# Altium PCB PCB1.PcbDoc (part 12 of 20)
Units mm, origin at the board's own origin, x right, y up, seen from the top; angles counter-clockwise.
Board outline 294.51 x 138.18 mm, 12 copper layers (Top Layer 1 _Signal, L2_GND, L3_Signals, L4_GND, L5_POWER, L6_Signals, L7_GND, L8_Signals, L9_GND, L10_POWER, L11_GND, Bottom Layer_Signals), stack 1.788 mm thick; 1254 components, 836 nets, 5699 pads, 2073 vias.
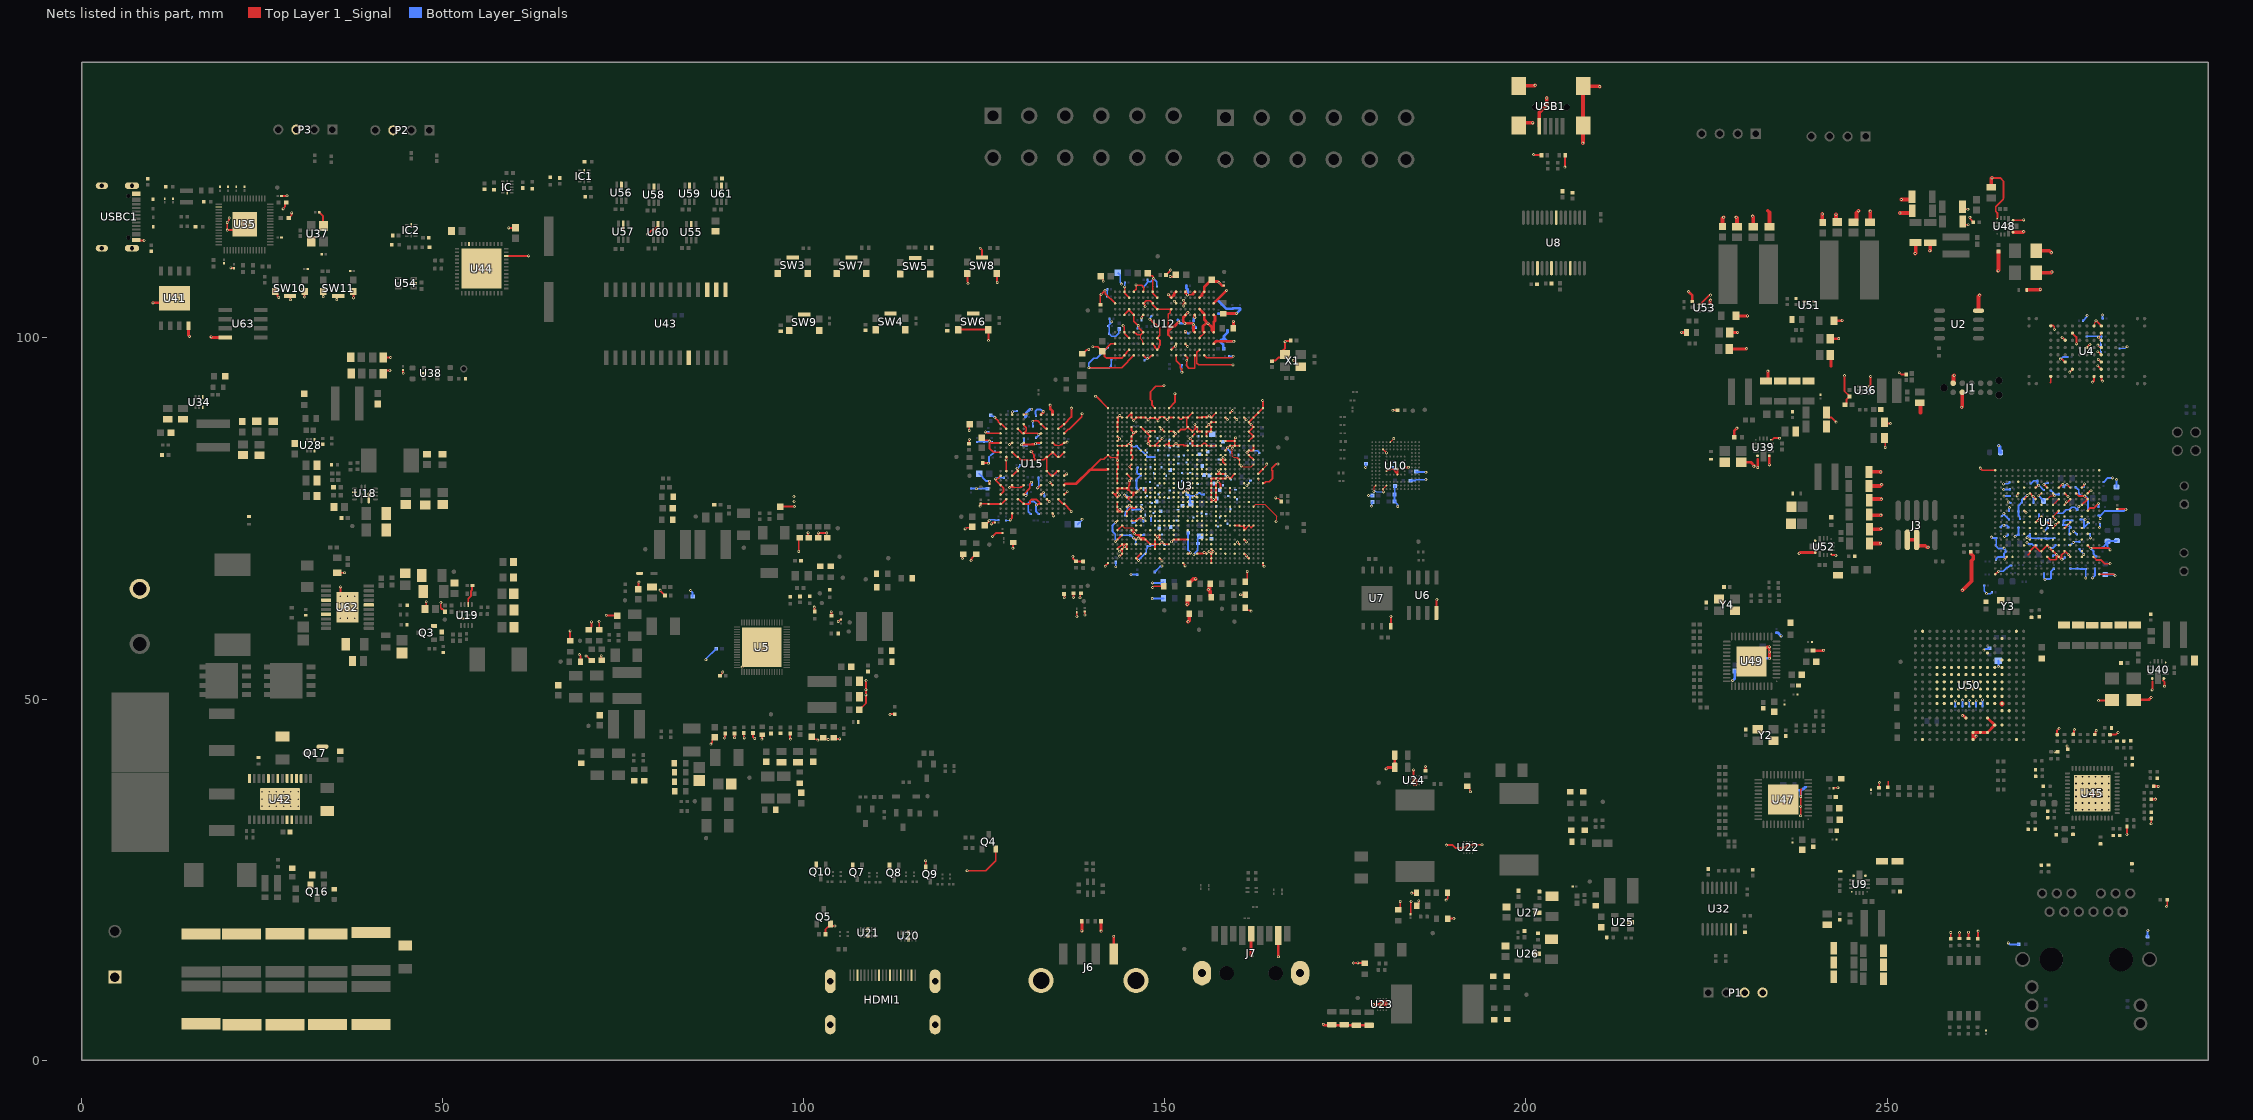
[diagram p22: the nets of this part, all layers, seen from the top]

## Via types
v1: diameter 0.4, hole 0.2, Top Layer 1 _Signal to Bottom Layer_Signals, 2009 vias
v2: diameter 0.508, hole 0.254, Top Layer 1 _Signal to Bottom Layer_Signals, 36 vias
v3: diameter 0.5, hole 0.2, Top Layer 1 _Signal to Bottom Layer_Signals, 12 vias
v4: diameter 1.27, hole 0.711, Top Layer 1 _Signal to Bottom Layer_Signals, 6 vias
v5: diameter 0.3, hole 0.2, Top Layer 1 _Signal to Bottom Layer_Signals, 5 vias
v6: diameter 0.254, hole 0.2, Top Layer 1 _Signal to Bottom Layer_Signals, 3 vias
v7: diameter 0.305, hole 0.2, Top Layer 1 _Signal to Bottom Layer_Signals, 1 vias
v8: diameter 0.254, hole 0.152, Top Layer 1 _Signal to Bottom Layer_Signals, 1 vias

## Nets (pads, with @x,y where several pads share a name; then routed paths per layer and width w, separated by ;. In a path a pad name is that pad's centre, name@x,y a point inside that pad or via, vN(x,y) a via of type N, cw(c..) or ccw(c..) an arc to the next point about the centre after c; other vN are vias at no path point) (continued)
GND: 1.1 2.1 3.1 4.1 5.1 6.1 C5.2 C6.1 C7.1 C8.1 C9.1 C10.1 C11.1 C12.1 C13.1 C14.1 C15.2 C16.1 C17.1 C18.2 C20.2 C21.2 C22.2 C23.2 C24.2 C25.2 C26.2 C27.1 C28.2 C29.2 C30.2 C31.1 C32.2 C33.2 C34.2 C35.2 C36.2 C37.2 C38.2 C39.2 C40.2 C41.2 C42.2 C43.1 C44.1 C46.2 C48.2 C49.2 C50.2 C52.2 C53.2 C54.2 C56.2 C57.2 C58.2 C59.2 C60.2 C61.2 C63.2 C64.2 C65.2 C66.2 C67.2 C68.2 C70.2 C71.2 C72.2 C73.2 C74.2 C75.2 C76.2 C77.2 C78.2 C79.2 C80.2 C81.2 C82.2 C83.2 C84.2 C85.2 C86.2 C87.2 C88.1 C89.2 C90.2 C91.2 C92.2 C93.2 C94.2 C95.2 C96.2 C97.1 C98.2 C99.2 C100.2 C101.2 C102.2 C103.2 C104.2 C105.2 C106.1 C107.2 C108.2 C111.2 C112.2 C113.2 C114.2 C115.2 C116.2 C117.2 C118.2 C119.2 C120.2 C121.1 C122.2 C123.2 C124.2 C125.2 C126.2 C127.2 C128.2 C129.2 C130.2 C131.2 C132.1 C133.1 C134.2 C135.2 C136.2 C137.2 C138.2 C139.2 C140.2 C141.2 C142.2 C143.2 C144.2 C145.2 C146.2 C147.2 C148.2 C149.2 C150.2 C151.2 C152.2 C153.2 C154.2 C155.2 C156.2 C158.2 C159.2 C160.2 C161.2 C162.2 C164.2 C165.2 C166.2 C167.2 C168.2 C169.2 C170.1 C171.2 C172.2 C173.2 C174.2 C175.2 C176.1 C177.1 C178.1 C180.2 C181.2 C182.2 C183.2 C184.1 C185.1 C187.2 C188.2 C189.2 C190.2 C191.2 C192.2 C194.1 C196.1 C197.1 C198.1 C199.1 C200.1 C201.1 C202.1 C203.2 C204.2 C205.1 C207.1 C208.1 C209.2 C210.1 C211.1 C212.2 C213.1 C214.1 C215.1 C216.1 C217.1 C220.1 C221.1 C222.2 C223.2 C224.2 C225.2 C226.2 C227.2 C228.2 C229.2 C230.1 C231.1 C232.1 C233.1 C234.2 C235.2 C236.1 C237.2 C238.2 C239.2 C240.2 C241.2 C242.2 C243.2 C244.2 C245.2 C246.2 C247.2 C248.2 C249.1 C250.2 C251.1 C252.1 C253.2 C254.2 C255.2 C256.1 C257.1 C258.2 C259.2 C260.1 C261.2 C262.1 C263.1 C264.2 C265.2 C266.2 C267.2 C268.2 C269.2 C270.2 C271.1 C272.1 C273.2 C274.2 C275.2 C276.2 C277.1 C278.1 C279.2 C280.2 C281.2 C282.1 C283.1 C284.1 C285.1 C286.2 C287.2 C288.2 C289.1 C290.1 C291.1 C292.2 C293.2 C294.2 C295.1 C296.1 C297.2 C298.1 C299.1 C300.1 C301.2 C302.1 C303.1 C304.1 C305.1 C306.2 C307.2 C308.1 C309.1 C310.1 C311.2 C312.2 C313.2 C314.1 C315.2 C316.2 C317.2 C318.2 C319.2 C320.2 C321.2 C322.2 C323.2 C324.2 C325.2 C326.2 C327.2 C328.2 C329.2 C330.2 C331.2 C332.2 C333.2 C334.2 C335.2 C336.2 C337.2 C338.2 C339.2 C340.2 C341.2 C342.2 C343.1 C344.2 C345.2 C346.2 C347.2 C348.2 C349.2 C350.2 C351.2 C352.1 C353.1 C354.2 C355.1 C356.2 C357.2 C358.2 C359.2 C360.2 C361.2 C362.2 C363.2 C364.2 C365.2 C366.2 C367.2 C368.2 C369.2 C370.2 C371.2 C372.2 C373.2 C374.2 C375.2 C376.2 C377.2 C378.2 C379.2 C380.2 C381.2 C382.2 C383.2 C384.2 C385.2 C386.2 C387.2 C388.2 C389.2 C390.2 C391.2 C392.2 C393.2 C394.2 C395.2 C396.2 C397.2 C398.2 C399.2 C400.2 C401.2 C402.2 C403.2 C404.2 C405.2 C406.2 C407.2 C408.2 C409.2 C410.2 C411.2 C412.2 C413.2 C414.2 C415.2 C416.2 C417.2 C418.2 C419.2 C420.2 C421.2 C422.2 C423.2 C424.2 C425.2 C426.2 C427.2 C428.2 C429.2 C430.2 C431.2 C432.2 C433.2 C434.2 C435.1 C437.1 C438.2 C439.2 C440.2 C441.2 C442.2 C443.2 C444.2 C446.2 C447.2 C448.2 C449.2 C450.2 C451.1 C452.2 C453.1 C454.2 C455.1 C456.2 C459.1 C460.2 C461.2 C462.1 C463.2 C464.2 C466.2 C467.2 C468.2 C470.2 C471.1 C472.1 C473.2 C483.2 C484.2 C485.1 C486.2 C487.1 C488.1 C489.2 C490.1 C491.1 C492.2 C493.1 C494.2 C495.2 C496.2 C497.2 C498.2 C500.1 C501.1 C502.2 C503.2 C504.2 C505.2 C506.2 C508.2 C509.1 C510.1 C511.2 C512.2 C513.2 C514.2 C515.2 C518.2 C519.2 C520.1 C521.1 C522.1 C523.1 C524.1 C525.1 C526.2 C528.2 C529.1 C530.1 C531.1 C532.1 C533.1 C534.1 C535.1 C536.1 C537.2 C538.1 C539.1 C540.1 C541.2 C542.2 C543.2 C544.1 C545.2 C547.2 C548.2 C550.2 C551.2 C552.2 C553.2 C554.2 C555.1 C556.1 C557.1 C558.1 C559.1 C560.2 C561.2 C562.1 C563.2 C564.1 C565.1 C566.1 C567.2 C568.1 C569.1 C570.1 C571.1 C572.1 C573.1 C574.1 C575.1 C576.1 C577.1 C578.1 C579.1 C580.1 C581.1 C582.1 C583.1 C584.1 C585.1 C586.2 C587.2 C588.1 C589.1 C590.1 C591.2 C592.1 C597.1 C598.2 C599.2 C600.1 C601.2 C603.2 C604.2 C605.2 C606.2 C611.1 C612.2 C613.1 C614.1 C615.2 C616.2 C617.2 C618.2 C619.1 C620.1 C621.1 C622.1 C623.1 C624.1 C625.1 C626.2 C627.1 C628.2 C629.2 C632.2 C635.1 C636.1 C637.2 C638.1 C639.1 C640.1 C641.2 C642.2 C643.2 C644.2 C645.2 C646.2 C647.2 C648.2 C649.1 C650.1 C651.2 C652.2 C653.1 C654.2 C655.2 C656.1 C657.2 C658.2 C659.2 C660.2 C661.1 C662.2 C663.1 C664.1 C665.2 C666.2 C667.2 C668.2 C669.2 C671.2 C672.2 C673.2 C674.2 C675.2 C676.2 C677.2 C679.2 C680.2 C681.2 C682.2 C683.2 C684.2 C685.2 C686.2 CN1.1 D1.2 D2.2 D5.1 D6.2 HDMI1.2 HDMI1.5 HDMI1.8 HDMI1.11 HDMI1.17 HDMI1.20 HDMI1.21 HDMI1.22 HDMI1.23 IC1.6 IC2.6 IC.6 J1.2 J1.10 J3.3 J3.5 J6.4 J6.Shell J7.4 J7.7 J7.Shell J8.1 P1.3 P1.4 P2.3 P3.3 Q3.2 Q4.2 Q5.2 Q7.2 Q8.2 Q9.2 Q10.2 Q16.2 Q17.2 R4.1 R6.1 R16.1 R17.1 R18.1 R19.1 R20.1 R33.1 R37.1 R40.2 R42.2 R52.1 R53.1 R69.1 R75.1 R76.2 R86.1 R88.1 R90.1 R91.1 R98.1 R99.1 R104.2 R105.1 R123.1 R126.2 R129.1 R131.1 R132.1 R134.2 R135.2 R137.1 R138.1 R142.1 R143.1 R144.2 R147.1 R157.1 R159.1 R162.1 R163.1 R176.2 R186.1 R190.2 R192.1 R210.1 R211.1 R212.2 R213.1 R215.2 R230.1 R233.1 R234.1 R235.2 R250.2 R256.1 R266.1 R267.1 R270.1 R271.1 R285.2 R297.1 R298.1 R302.1 R339.2 R375.1 R377.1 R382.1 R384.1 R386.1 R388.1 R390.1 R392.1 R394.1 R396.1 R397.1 R399.2 R402.1 SW3.3 SW3.4 SW3.5 SW4.3 SW4.4 SW4.5 SW5.3 SW5.4 SW5.5 SW6.3 SW6.4 SW6.5 SW7.3 SW7.4 SW7.5 SW8.3 SW8.4 SW8.5 SW9.3 SW9.4 SW9.5 SW10.1 SW10.2 SW10.5 SW11.1 SW11.2 SW11.5 U1.A1 U1.A19 U1.B16 U1.C5 U1.C6 U1.C8 U1.C10 U1.C12 U1.C14 U1.D4 U1.D7 U1.D9 U1.D11 U1.D13 U1.D15 U1.D16 U1.E5 U1.F4 U1.F6 U1.F8 U1.F10 U1.F12 U1.F14 U1.F16 U1.G5 U1.G7 U1.G9 U1.G11 U1.G13 U1.G15 U1.H4 U1.H6 U1.H8 U1.H10 U1.H12 U1.H14 U1.H16 U1.J5 U1.J7 U1.J9 U1.J11 U1.J13 U1.J15 U1.K4 U1.K6 U1.K8 U1.K10 U1.K12 U1.K14 U1.K16 U1.L5 U1.L7 U1.L9 U1.L11 U1.L13 U1.L15 U1.M4 U1.M6 U1.M8 U1.M10 U1.M12 U1.M14 U1.N5 U1.N7 U1.N9 U1.N11 U1.N13 U1.N15 U1.P4 U1.P6 U1.P8 U1.P10 U1.P12 U1.P14 U1.R3 U1.R5 U1.T16 U1.U16 U1.W1 U1.W19 U2.4 U3.A1 U3.A11 U3.A14 U3.A34 U3.AA3 U3.AA6 U3.AA8 U3.AA10 U3.AA11 U3.AA16 U3.AA17 U3.AA18 U3.AA19 U3.AA20 U3.AA21 U3.AA22 U3.AA23 U3.AA24 U3.AA31 U3.AB3 U3.AB5 U3.AB6 U3.AB7 U3.AB8 U3.AB10 U3.AB11 U3.AB16 U3.AB17 U3.AB18 U3.AB19 U3.AB20 U3.AB24 U3.AB27 U3.AB29 U3.AB32 U3.AC3 U3.AC4 U3.AC5 U3.AC8 U3.AC10 U3.AC11 U3.AC12 U3.AC16 U3.AC20 U3.AC21 U3.AC24 U3.AC27 U3.AD5 U3.AD8 U3.AD10 U3.AD11 U3.AD12 U3.AD16 U3.AD20 U3.AD21 U3.AD24 U3.AD25 U3.AD26 U3.AE3 U3.AE6 U3.AE7 U3.AE9 U3.AE11 U3.AE12 U3.AE13 U3.AE14 U3.AE15 U3.AE16 U3.AE18 U3.AE19 U3.AE20 U3.AE21 U3.AE24 U3.AE26 U3.AF4 U3.AF7 U3.AF8 U3.AF11 U3.AF12 U3.AF13 U3.AF14 U3.AF15 U3.AF16 U3.AF21 U3.AF22 U3.AF24 U3.AF25 U3.AF27 U3.AF28 U3.AF29 U3.AF30 U3.AF31 U3.AF32 U3.AG3 U3.AG6 U3.AG7 U3.AG10 U3.AG12 U3.AG15 U3.AG18 U3.AG21 U3.AG22 U3.AG30 U3.AH4 U3.AH8 U3.AH11 U3.AH12 U3.AH15 U3.AH21 U3.AH22 U3.AH23 U3.AJ3 U3.AJ7 U3.AJ8 U3.AJ9 U3.AJ11 U3.AJ12 U3.AJ15 U3.AJ16 U3.AJ18 U3.AJ21 U3.AJ22 U3.AJ23 U3.AJ30 U3.AK4 U3.AK5 U3.AK7 U3.AK10 U3.AK11 U3.AK12 U3.AK13 U3.AK14 U3.AK23 U3.AK28 U3.AK29 U3.AL3 U3.AL4 U3.AL5 U3.AL11 U3.AL13 U3.AL23 U3.AL25 U3.AM4 U3.AM8 U3.AM9 U3.AM18 U3.AM20 U3.AM22 U3.AM23 U3.AM24 U3.AM26 U3.AM28 U3.AM30 U3.AN7 U3.AN12 U3.AN23 U3.AN31 U3.AP1 U3.AP17 U3.AP23 U3.AP34 U3.B6 U3.B19 U3.B24 U3.B27 U3.B33 U3.C3 U3.C4 U3.C5 U3.C6 U3.C7 U3.C8 U3.C9 U3.C10 U3.C11 U3.C12 U3.C13 U3.C14 U3.C15 U3.C16 U3.C17 U3.C18 U3.C20 U3.C21 U3.C22 U3.C23 U3.C26 U3.C28 U3.C30 U3.C32 U3.D3 U3.D23 U3.D24 U3.D31 U3.E3 U3.E6 U3.E8 U3.E12 U3.E18 U3.E20 U3.E22 U3.E23 U3.E32 U3.F3 U3.F7 U3.F9 U3.F10 U3.F11 U3.F13 U3.F14 U3.F15 U3.F16 U3.F19 U3.F20 U3.F21 U3.F22 U3.F23 U3.F31 U3.G3 U3.G6 U3.G10 U3.G15 U3.G19 U3.G21 U3.G22 U3.G25 U3.G32 U3.H3 U3.H6 U3.H10 U3.H12 U3.H14 U3.H19 U3.H22 U3.H25 U3.H26 U3.H28 U3.H31 U3.J3 U3.J4 U3.J5 U3.J6 U3.J10 U3.J11 U3.J12 U3.J13 U3.J14 U3.J15 U3.J16 U3.J18 U3.J19 U3.J20 U3.J21 U3.J22 U3.J23 U3.J24 U3.J25 U3.J27 U3.J28 U3.J29 U3.J32 U3.K3 U3.K6 U3.K8 U3.K9 U3.K18 U3.K21 U3.K22 U3.K26 U3.K31 U3.K32 U3.L1 U3.L3 U3.L6 U3.L9 U3.L16 U3.L19 U3.L20 U3.L21 U3.L22 U3.L25 U3.L26 U3.L31 U3.M3 U3.M6 U3.M9 U3.M11 U3.M14 U3.M15 U3.M18 U3.M20 U3.M22 U3.M25 U3.M26 U3.M29 U3.M32 U3.N3 U3.N6 U3.N9 U3.N11 U3.N14 U3.N15 U3.N18 U3.N20 U3.N22 U3.N25 U3.N26 U3.N29 U3.N32 U3.P1 U3.P3 U3.P6 U3.P8 U3.P9 U3.P11 U3.P14 U3.P15 U3.P18 U3.P19 U3.P20 U3.P21 U3.P22 U3.P25 U3.P26 U3.P34 U3.R3 U3.R5 U3.R8 U3.R9 U3.R11 U3.R13 U3.R15 U3.R18 U3.R19 U3.R20 U3.R21 U3.R22 U3.R23 U3.R24 U3.R25 U3.R26 U3.R28 U3.R33 U3.T3 U3.T6 U3.T9 U3.T11 U3.T13 U3.T15 U3.T18 U3.T19 U3.T20 U3.T23 U3.T24 U3.T25 U3.T26 U3.T27 U3.T33 U3.U3 U3.U12 U3.U13 U3.U15 U3.U16 U3.U17 U3.U19 U3.U20 U3.U23 U3.U24 U3.U30 U3.U31 U3.U34 U3.V3 U3.V4 U3.V5 U3.V8 U3.V9 U3.V10 U3.V11 U3.V15 U3.V18 U3.V19 U3.V23 U3.V24 U3.V25 U3.V27 U3.V30 U3.W2 U3.W3 U3.W6 U3.W7 U3.W9 U3.W10 U3.W11 U3.W12 U3.W15 U3.W16 U3.W17 U3.W18 U3.W19 U3.W20 U3.W23 U3.W24 U3.W27 U3.Y3 U3.Y5 U3.Y6 U3.Y8 U3.Y9 U3.Y10 U3.Y11 U3.Y12 U3.Y13 U3.Y14 U3.Y15 U3.Y16 U3.Y17 U3.Y18 U3.Y19 U3.Y20 U3.Y23 U3.Y24 U3.Y28 U4.G2 U4.G3 U4.G4 U4.G5 U4.G6 U4.G7 U4.G8 U4.G9 U4.H2 U4.H9 U4.J5 U4.L3 U4.L8 U4.M4 U4.M7 U4.P2 U4.P9 U5.69 U6.4 U7.4 U8.7 U8.18 U8.21 U8.25 U9.1 U9.9 U9.11 U10.A6 U10.C4 U10.H10 U10.J5 U10.K8 U10.N2 U10.N5 U10.P4 U12.A3 U12.A10 U12.AB3 U12.AB5 U12.AB8 U12.AB10 U12.C1 U12.C5 U12.C8 U12.C12 U12.D2 U12.D4 U12.D9 U12.D11 U12.E1 U12.E5 U12.E8 U12.E12 U12.G1 U12.G3 U12.G5 U12.G8 U12.G10 U12.G12 U12.J1 U12.J3 U12.J10 U12.J12 U12.K2 U12.K4 U12.K9 U12.K11 U12.N2 U12.N4 U12.N9 U12.N11 U12.P1 U12.P3 U12.P10 U12.P12 U12.T1 U12.T3 U12.T5 U12.T8 U12.T10 U12.T12 U12.V1 U12.V5 U12.V8 U12.V12 U12.W2 U12.W4 U12.W9 U12.W11 U12.Y1 U12.Y5 U12.Y8 U12.Y12 U13.1 U14.1 U15.A3 U15.A10 U15.AB3 U15.AB5 U15.AB8 U15.AB10 U15.C1 U15.C5 U15.C8 U15.C12 U15.D2 U15.D4 U15.D9 U15.D11 U15.E1 U15.E5 U15.E8 U15.E12 U15.G1 U15.G3 U15.G5 U15.G8 U15.G10 U15.G12 U15.J1 U15.J3 U15.J10 U15.J12 U15.K2 U15.K4 U15.K9 U15.K11 U15.N2 U15.N4 U15.N9 U15.N11 U15.P1 U15.P3 U15.P10 U15.P12 U15.T1 U15.T3 U15.T5 U15.T8 U15.T10 U15.T12 U15.V1 U15.V5 U15.V8 U15.V12 U15.W2 U15.W4 U15.W9 U15.W11 U15.Y1 U15.Y5 U15.Y8 U15.Y12 U16.2 U17.2 U18.2 U18.10 U19.2 U19.10 U20.3 U20.8 U21.3 U21.8 U22.B2 U22.B3 U22.B4 U22.C1 U22.C2 U22.C3 U22.C4 U23.B2 U23.B3 U23.B4 U23.C1 U23.C2 U23.C3 U23.C4 U24.B2 U24.B3 U24.B4 U24.C1 U24.C2 U24.C3 U24.C4 U25.2 U26.2 U27.2 U28.3 U28.4 U29.2 U30.2 U31.2 U32.15 U33.2 U34.3 U34.4 U35.47 U35.61 U36.3 U37.2 U37.4 U38.2 U39.1 U39.9 U39.11 U40.1 U40.9 U40.11 U41.4 U41.9 U42.9 U42.10 U42.17 U42.18 U42.19 U42.20 U42.22 U42.24 U42.28 U42.29 U43.10 U43.15 U43.16 U43.17 U44.10 U44.46 U44.49 U45.49 U47.49 U48.1 U48.9 U48.11 U49.49 U50.B1 U50.B16 U50.C5 U50.C12 U50.D2 U50.D5 U50.D6 U50.D7 U50.D8 U50.D9 U50.D10 U50.D11 U50.D12 U50.D14 U50.E6 U50.E7 U50.E8 U50.E9 U50.E10 U50.E11 U50.E14 U50.F4 U50.F6 U50.F7 U50.F8 U50.F9 U50.F10 U50.F11 U50.F13 U50.F15 U50.G6 U50.G7 U50.G8 U50.G9 U50.G10 U50.G11 U50.G15 U50.H6 U50.H7 U50.H8 U50.H9 U50.H10 U50.H11 U50.H15 U50.H16 U50.J6 U50.J7 U50.J8 U50.J9 U50.J10 U50.J11 U50.J13 U50.K6 U50.K7 U50.K8 U50.K9 U50.K10 U50.K11 U50.L6 U50.L7 U50.L8 U50.L9 U50.L10 U50.L11 U50.M6 U50.M7 U50.M8 U50.M9 U50.M10 U50.M11 U50.N6 U50.N7 U50.N8 U50.N9 U50.N10 U50.N11 U50.R1 U50.R16 U51.3 U51.4 U52.1 U52.9 U52.11 U53.3 U53.4 U54.2 U55.2 U56.2 U57.2 U58.2 U59.2 U60.2 U61.2 U62.6 U62.14 U62.17 U62.21 U63.4 USB1.5 USB1.6 USB1.7 USB1.8 USB1.9 USBC1.A1_B12 USBC1.B1_A12 USBC1.S1 USBC1.S2 USBC1.S3 USBC1.S4 X1.2 X1.4 Y2.2 Y2.4 Y3.3 Y4.2 Y4.4 | length 1028.4
  Top Layer 1 _Signal w0.089: v1@178.963,78.776 178.963,79.406
  Top Layer 1 _Signal w0.132: 129.071,79.28 129.087,79.295 129.784,79.295 129.792,79.304 129.947,79.304 ; 135.029,85.146 135.511,85.146 135.548,85.183 ; 146.644,100.428 146.68,100.393 146.68,99.854 146.972,99.562 146.972,99.221 U12.G3@147.004,99.189 ; 178.963,79.406 179.007,79.406 179.172,79.57 U10.N2@179.204,79.57 ; v1(180.267,78.675) 180.226,78.716 180.226,79.047 U10.P4@180.204,79.07 U10.N5@180.704,79.57
  Top Layer 1 _Signal w0.152: 142.58,83.453 142.585,83.448 143.139,83.448 143.21,83.376 143.281,83.305 143.281,83.27 143.429,83.122 143.436,83.115 v1(143.436,83.048) ; U3.AF4@144.079,74.028 144.359,73.749 144.359,73.725 144.579,73.725 144.607,73.698 145.562,73.698 145.789,73.471 v1(145.789,72.899) ; v1(151.316,105.079) 151.316,105.053 151.554,104.815 U12.P10@151.554,104.789 ; v1(152.591,105.213) 152.641,105.163 152.641,105.055 152.854,104.842 U12.T10@152.854,104.789 152.755,104.888 152.629,104.888 152.539,104.799 152.539,104.491 v1(152.608,104.423) ; U3.W27@159.029,78.578 159.039,78.587 159.039,79.219 U3.V27@159.029,79.228 ; v1(159.372,84.748) 159.359,84.735 159.359,84.305 159.293,84.239 159.293,84.113 159.359,84.047 159.359,83.645 159.547,83.458 159.802,83.458 159.86,83.399 160.04,83.399 ; U3.M29@160.329,83.128 160.346,83.111 160.346,82.495 U3.N29@160.329,82.478 160.329,82.435 160.491,82.274 v1(160.585,82.274) 160.652,82.274 160.768,82.158 161.959,82.158 U3.N32@162.279,82.478 ; v1(161.372,84.113) 161.372,84.074 161.629,83.817 U3.L31@161.629,83.778 ; U3.AB32@162.279,76.628 162.599,76.948 163.815,76.948 165.483,75.28 165.483,74.67 v1(165.409,74.595) ; U3.T33@162.929,80.528 162.929,80.483 163.028,80.384 163.028,80.313 163.079,80.262 v6(163.079,80.235) ; U3.P34@163.579,81.828 164.06,82.308 164.06,82.473 v1(164.107,82.52) v1@164.107,82.5 ; v1(165.354,77.842) 165.402,77.794 165.693,77.794 166.121,77.365 R69.1@166.121,77.34 ; U10.A6@181.204,85.57 181.669,86.035 181.669,86.046 v1(181.692,86.07) ; v1(271.015,78.148) 271.032,78.148 271.364,78.48 U1.L5@271.381,78.48 ; U1.K6@272.181,77.68 272.678,78.177 v1(273.201,78.177) 273.201,78.218 272.981,78.438 U1.J5@272.981,78.48 ; U1.J7@272.981,76.88 273.017,76.88 273.429,77.292 273.429,77.328 U1.H6@273.781,77.68 ; U1.G7@274.581,76.88 274.868,77.167 274.868,77.293 v1(274.864,77.297) ; U4.H2@278.672,101.669 278.728,101.726 278.728,102.097 278.938,102.307 v1(278.938,102.374) ; v1(279.194,99) 279.468,98.726 279.615,98.726 U4.G5@279.672,98.669 ; U4.G4@279.672,99.669 279.308,100.033 v1(279.308,100.102) 279.615,100.409 279.615,100.612 U4.G3@279.672,100.669
  Top Layer 1 _Signal w0.178: v1(153.132,105.967) 153.809,105.967 153.892,106.051
  Top Layer 1 _Signal w0.2: U57.2@75.008,115.799 75.008,114.933 75.169,114.772 v1(75.169,114.718) ; v1(78.37,114.353) 78.995,114.978 79.286,114.978 79.823,115.516 U60.2@79.823,115.766 ; C16.1@137.804,62.001 137.808,61.997 137.808,61.447 v1(137.811,61.444) ; C430.2@138.566,97.817 138.641,97.817 139.195,98.371 139.418,98.371 v1(139.456,98.41) ; v1(139.47,95.877) 139.479,95.887 144.003,95.887 U12.E1@145.704,97.589 ; v1(140.019,98.78) 140.686,98.78 C340.2@141.306,98.16 141.656,98.51 141.924,98.51 142.047,98.633 142.047,98.709 142.527,99.189 U12.A3@143.104,99.189 ; C367.2@141.124,108.56 141.47,108.214 v1(141.47,107.842) ; v1(141.739,68.385) 141.739,68.437 U3.AP1@142.129,68.828 ; U3.AL3@143.429,70.778 U3.AK4@144.079,71.428 U3.AK4@144.095,71.428 ; v1(143.733,70.465) 144.047,70.778 U3.AL4@144.079,70.778 ; v1(143.743,69.792) U3.AM4@144.079,70.128 U3.AL4@144.079,70.778 ; v1(144.222,101.706) 144.222,101.652 144.404,101.47 U12.C5@144.404,100.789 144.433,100.76 144.433,100.61 U12.D4@145.054,99.989 ; v1(144.434,107.065) 144.419,107.05 144.419,106.404 U12.C12@144.404,106.389 144.433,106.36 144.433,106.21 U12.D11@145.054,105.589 ; v1(144.451,71.087) v1@144.436,71.087 ; U3.AL5@144.729,70.778 U3.AK5@144.729,71.428 U3.AK4@144.095,71.428 ; U12.E12@145.704,106.389 145.704,106.429 146.007,106.732 v1(146.007,107.345) 146.046,107.307 146.181,107.307 146.224,107.263 146.833,107.263 147.064,107.032 147.064,106.586 147.033,106.555 147.033,106.418 U12.G12@147.004,106.389 ; v1(146.743,102.786) 146.781,102.825 146.781,102.925 147.004,103.148 U12.G8@147.004,103.189 ; U12.G1@147.004,97.589 147.418,97.175 147.537,97.175 v1(147.576,97.137) 147.614,97.175 147.798,97.175 148.137,97.514 148.189,97.514 148.264,97.589 U12.J1@148.304,97.589 U12.J1@148.304,97.623 ; C316.2@147.62,108.922 147.919,108.622 148.244,108.622 148.415,108.452 148.415,108.25 v1(148.453,108.211) 148.453,108.157 148.304,108.008 U12.J12@148.304,106.389 148.333,106.36 148.333,106.21 U12.K11@148.954,105.589 ; v1(147.924,102.587) 147.957,102.587 148.548,101.995 148.7,101.995 149.313,101.381 149.313,100.348 U12.K4@148.954,99.989 ; U3.E12@149.279,87.678 149.279,87.656 149.501,87.434 v1(149.501,87.412) 149.545,87.412 U3.F13@149.929,87.028 ; C325.2@150.175,108.727 150.749,109.301 150.749,109.369 v1(150.788,109.408) ; U3.F14@150.579,87.028 150.612,87.028 150.693,87.11 151.115,87.11 151.197,87.028 U3.F15@151.229,87.028 151.492,86.765 v1(151.492,86.754) ; v1(150.739,108.502) 151.296,108.502 C315.2@151.541,108.747 ; U12.N2@150.904,98.389 151.321,98.806 151.46,98.806 v1(151.498,98.844) 151.498,98.867 151.526,98.895 151.526,99.16 U12.P3@151.554,99.189 ; U12.P1@151.554,97.589 151.554,96.86 152.139,96.275 152.139,95.846 152.318,95.667 152.318,95.284 v1(152.356,95.246) ; U3.AP17@152.529,68.828 152.529,68.795 152.775,68.549 152.775,68.47 v1(152.814,68.432) ; U12.T3@152.854,99.189 152.854,99.148 153.161,98.842 v1(153.161,98.817) ; U12.W2@154.804,98.389 154.43,98.015 154.43,96.524 154.692,96.261 v1(159.434,96.261) ; U12.Y1@155.454,97.589 155.813,97.23 159.243,97.23 v1(159.473,97.46) ; C515.2@182.348,20.834 182.597,21.083 v1(182.597,21.98) ; C281.2@184.037,20.2 184.037,21.858 184.107,21.927 v1(184.107,21.981) ; v1(184.194,23.116) 184.775,23.116 C511.2@184.846,23.188 ; C514.2@184.865,21.379 185.14,21.654 185.14,22.041 v1(185.161,22.062) ; v1(188.941,22.15) 188.941,22.204 189.141,22.404 C513.2@189.141,23.192 ; C498.2@191.879,37.901 191.954,37.901 192.229,37.626 192.229,37.301 192.317,37.214 v1(192.317,37.16) ; 192.18,29.735 192.264,29.819 v1(193.918,29.819) ; v1(238.028,33.842) 238.032,33.846 238.032,35.121 238.043,35.132 238.043,36.509 v1(238.049,36.515) 238.036,36.528 238.036,37.423 238.176,37.563 ; C652.2@242.576,37.636 242.576,37.646 242.616,37.686 242.626,37.686 242.653,37.713 v1(243.206,37.713) ; C627.1@248.915,37.705 248.947,37.738 248.947,38.402 v1(248.979,38.434) ; C628.2@250.125,37.784 250.18,37.839 250.18,38.601 ; U48.11@267.456,116.277 268.291,116.277 268.332,116.318 268.887,116.318 v1(268.925,116.356) ; U3.AL4@144.079,70.778 144.112,70.778 144.421,71.087 v1@144.436,71.087 ; U3.AK4@144.095,71.428 v1@144.436,71.087
  Top Layer 1 _Signal w0.203: C402.2@122.878,85.331 122.884,85.326 122.909,85.352 122.909,85.93 v1(122.94,85.961) ; v1(122.909,87.193) 122.909,87.979 C393.2@122.949,88.018 ; v1(125.147,86.999) 125.2,86.999 125.428,86.771 U15.V12@127.25,86.771 ; v1(126.475,88.974) 126.916,88.533 126.916,88.415 127.25,88.082 U15.Y12@127.25,88.071 127.278,88.042 127.428,88.042 U15.W11@128.05,87.421 ; U15.AB10@128.85,89.371 128.875,89.395 128.875,89.728 v1(128.899,89.753) ; U15.W9@129.65,87.421 130.272,86.799 130.422,86.799 U15.V8@130.45,86.771 ; U15.Y8@130.45,88.071 130.478,88.042 130.478,87.902 130.81,87.57 130.81,87.131 U15.V8@130.45,86.771 ; U15.AB8@130.45,89.371 130.478,89.399 130.797,89.399 130.862,89.464 v1(130.916,89.464) ; v1(132.546,86.667) 132.493,86.667 132.39,86.771 U15.V8@130.45,86.771 ; 135.548,85.183 135.723,85.183 136.01,85.471 U15.T1@136.05,85.471 136.078,85.499 136.287,85.499 136.334,85.546 136.434,85.546 v1(136.472,85.584) ; C341.2@141.074,104.611 141.074,105.941 v1(141.168,106.035) 141.184,106.035 141.699,106.551 v1(141.714,106.551) 141.752,106.513 141.752,106.141 U12.A10@143.104,104.789 ; U12.C8@144.404,103.189 145.026,103.811 ; U3.AB5@144.729,76.628 144.761,76.628 144.919,76.786 145.082,76.786 v1(145.12,76.824) ; U12.D9@145.054,103.989 145.026,103.961 145.043,103.961 145.082,103.921 145.082,103.811 U12.E8@145.704,103.189 145.704,102.314 146.321,101.698 146.358,101.66 146.358,101.435 U12.G5@147.004,100.789 146.644,100.428 146.205,100.428 145.997,100.636 145.897,100.636 145.744,100.789 U12.E5@145.704,100.789 ; U3.AE6@145.379,74.678 U3.AE7@146.029,74.678 146.375,75.023 146.943,75.023 146.986,74.98 v1(147.004,74.98) ; v1(147.266,104.375) 147.266,104.527 U12.G10@147.004,104.789 147.044,104.789 147.33,105.075 147.365,105.075 147.44,105.149 147.944,105.149 U12.J10@148.304,104.789 148.332,104.761 148.332,104.611 U12.K9@148.954,103.989 U12.N9@150.904,103.989 150.904,103.949 150.715,103.76 150.715,103.509 150.455,103.249 150.455,100.975 ; U12.T1@152.854,97.589 152.854,97.549 153.136,97.267 153.136,97.217 153.07,97.151 153.07,96.95 v1(153.033,96.913) 153.031,96.911 153.031,96.119 153.337,95.814 153.715,95.814 153.748,95.781 154.035,95.781 154.154,95.9 U12.V1@154.154,97.589 ; U3.AP23@156.429,68.828 U3.AN23@156.429,69.478 156.429,70.108 156.687,70.365 v1(156.687,70.419) ; v1(160.482,64.438) 161.087,64.438 C253.2@161.115,64.466 ; C37.2@161.113,66.27 161.387,66.544 161.387,67.086 161.407,67.107 v1(161.407,67.666) ; C254.2@161.143,62.631 161.143,62.556 161.416,62.282 161.785,62.282 161.892,62.175 v1(161.946,62.175) ; 164.824,81.664 164.824,81.959 165.41,82.545 v1(165.645,82.545) ; 269.493,69.912 269.757,70.176 269.757,70.446 269.791,70.48 U1.N15@269.781,70.48 U1.M14@270.581,71.28 270.581,71.012 271.113,70.48 U1.L15@271.381,70.48 U1.K14@272.181,71.28 272.181,71.278 272.554,70.905 v1(272.554,70.902) 272.556,70.902 272.979,70.48 U1.J15@272.981,70.48
  Top Layer 1 _Signal w0.229: v1(266.308,69.361) 266.311,69.361 266.53,69.581 266.53,69.602 266.581,69.653 U1.U16@266.581,69.68 ; U1.M10@270.581,74.48 270.608,74.48 270.875,74.747 270.928,74.747 v1(270.961,74.78) 270.994,74.813 270.994,74.893 U1.L9@271.381,75.28 ; U1.K10@272.181,74.48 U1.J11@272.981,73.68 272.981,73.699 273.331,74.049 273.331,74.167 v1(273.364,74.2) 273.396,74.232 273.506,74.232 273.753,74.48 U1.H10@273.781,74.48 ; v1(273.31,74.87) 273.31,74.924 272.981,75.253 U1.J9@272.981,75.28 U1.H8@273.781,76.08 ; U1.G11@274.581,73.68 274.6,73.699 274.676,73.699 v1(275.064,74.088) 275.064,74.136 275.381,74.453 U1.F10@275.381,74.48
